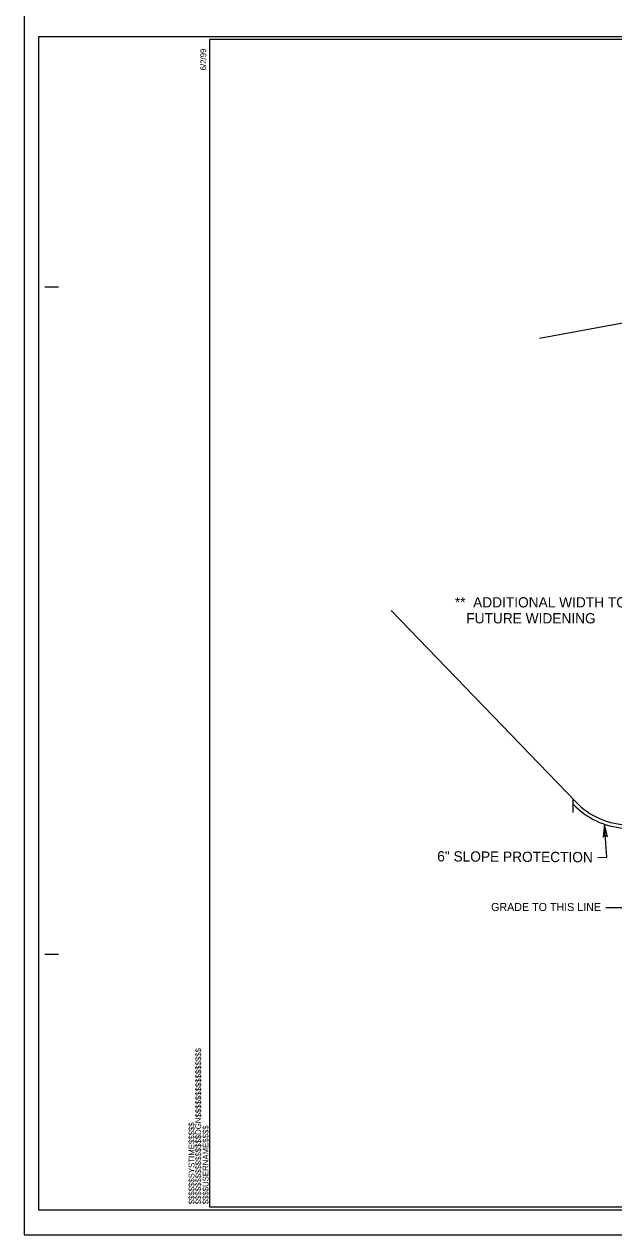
# Model space of a CAD drawing. Extents: x 981824 to 982276, y 44828 to 45204.
# Drawn here: x 982094.4 to 982136.8, y 44914 to 45001.1 of the extents above; entities that cross this region are included whole.
import ezdxf

# ---------------------------------------------------------------- set-up
doc = ezdxf.new("R2010")
doc.units = 0
for name, color, linetype in [('Old_Level_1', 7, 'Continuous'), ('Old_Level_11', 7, 'Continuous'), ('Old_Level_18', 7, 'Continuous'), ('Old_Level_3', 7, 'Continuous'), ('Old_Level_40', 7, 'Continuous'), ('Old_Level_41', 7, 'Continuous'), ('Old_Level_50', 7, 'Continuous'), ('Old_Level_51', 7, 'Continuous'), ('Old_Level_52', 7, 'Continuous'), ('Prop Terminator CELL', 7, 'Continuous'), ('Typical Guardrail CELL', 7, 'Continuous')]:
    doc.layers.add(name, color=color, linetype=linetype)

msp = doc.modelspace()

# ---------------------------------------------------------------- linework, layer by layer
at = {"layer": 'Old_Level_1'}
for p, q in [((982131.486, 44978.47), (982141.024, 44980.249)), ((982136.255, 44937.513), (982137.674, 44937.513))]:
    msp.add_line(p, q, dxfattribs=at)
at = {"layer": 'Old_Level_11'}
for p, q in [((982134.089, 44945.114), (982120.784, 44958.877)), ((982134.089, 44945.114), (982133.908, 44945.302)), ((982133.913, 44944.36), (982133.908, 44945.302))]:
    msp.add_line(p, q, dxfattribs=at)
for radius, end in [(5.58, 266.07811), (5.331, 270)]:
    msp.add_arc((982137.941, 44948.8), radius, 223.74207, end, dxfattribs=at)
at = {"layer": 'Old_Level_18'}
msp.add_line((982107.72, 44915.969), (982107.72, 44915.969), dxfattribs=at)
msp.add_line((982107.72, 44915.969), (982107.72, 44915.969), dxfattribs=at)
msp.add_lwpolyline([(982227.72, 44999.969), (982107.72, 44999.969), (982107.72, 44915.969), (982227.72, 44915.969)], close=True, dxfattribs=at)
at = {"layer": 'Old_Level_40'}
msp.add_line((982107.72, 44915.969), (982107.72, 44915.969), dxfattribs=at)
msp.add_line((982107.72, 44915.969), (982107.72, 44915.969), dxfattribs=at)
msp.add_line((982107.72, 44915.969), (982107.72, 44915.969), dxfattribs=at)
msp.add_line((982107.72, 44915.969), (982107.72, 44915.969), dxfattribs=at)
at = {"layer": 'Old_Level_41'}
for p, q in [((982095.84, 44982.169), (982096.84, 44982.169)), ((982095.84, 44934.169), (982096.84, 44934.169))]:
    msp.add_line(p, q, dxfattribs=at)
msp.add_lwpolyline([(982110.72, 44915.969), (982110.72, 44915.969)], dxfattribs=at)
at = {"layer": 'Old_Level_50'}
msp.add_line((982094.36, 44913.969), (982094.36, 44913.969), dxfattribs=at)
msp.add_lwpolyline([(982228.72, 45000.173), (982095.4, 45000.173), (982095.4, 44915.765), (982228.72, 44915.765)], close=True, dxfattribs=at)
at = {"layer": 'Old_Level_51'}
msp.add_lwpolyline([(982229.08, 45001.969), (982094.36, 45001.969), (982094.36, 44913.969), (982229.08, 44913.969)], close=True, dxfattribs=at)
at = {"layer": 'Old_Level_52'}
msp.add_line((982095.4, 44915.765), (982095.4, 44915.765), dxfattribs=at)
at = {"layer": 'Prop Terminator CELL'}
msp.add_lwpolyline([(982136.381, 44942.615), (982136.159, 44943.501), (982136.067, 44942.587), (982136.218, 44942.713)], close=True, dxfattribs=at)
at = {"layer": 'Typical Guardrail CELL'}
msp.add_lwpolyline([(982135.674, 44941.108), (982136.337, 44941.134), (982136.159, 44943.501)], dxfattribs=at)

# ---------------------------------------------------------------- texts
at = {"layer": 'Old_Level_11'}
msp.add_text('6" SLOPE PROTECTION', height=0.73819, rotation=359.65623, dxfattribs=at).set_placement((982124.109, 44940.835))
at = {"layer": 'Old_Level_3'}
for s, p in [('**  ADDITIONAL WIDTH TO ALLOW FOR ', (982125.382, 44959.108)), ('   FUTURE WIDENING', (982125.382, 44957.96))]:
    msp.add_text(s, height=0.73819, rotation=360, dxfattribs=at).set_placement(p)
msp.add_text('GRADE TO THIS LINE', height=0.576, dxfattribs=at).set_placement((982127.994, 44937.267))
at = {"layer": 'Old_Level_41'}
for s, p in [('6/2/99', (982107.468, 44997.749)), ('$$$$$$$$$$$$$$$$DGN$$$$$$$$$$$$$$$$', (982107.108, 44916.158)), ('$$$$$$SYSTIME$$$$$', (982106.624, 44916.158)), ('$$$$USERNAME$$$$', (982107.634, 44916.159))]:
    msp.add_text(s, height=0.42, rotation=90, dxfattribs=at).set_placement(p)

doc.saveas('drawing.dxf')
